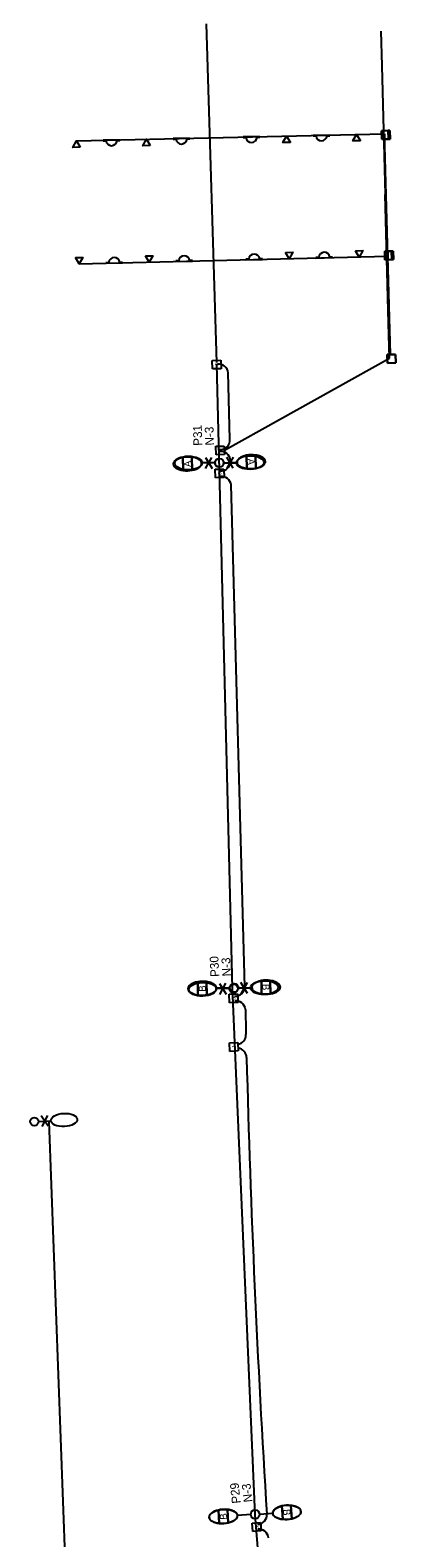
# Model space of a CAD drawing. Extents: x 925407 to 930994, y 604905 to 637063.
# Drawn here: x 929545 to 929754, y 612493 to 613355 of the extents above; entities that cross this region are included whole.
import ezdxf

# ---------------------------------------------------------------- set-up
doc = ezdxf.new("R2010")
doc.units = 0
for name, color, linetype in [('ActivePointCell_dp', 7, 'Continuous'), ('Conduit', 7, 'Continuous'), ('ConduitDB', 7, 'Continuous'), ('ConduitJB', 7, 'Continuous'), ('ConduitOT', 7, 'Continuous'), ('GPKDrCellIns_dp', 7, 'Continuous'), ('LightingMisc', 7, 'Continuous'), ('LiteCond_ep', 7, 'Continuous'), ('Miscellaneous2', 7, 'Continuous'), ('Miscellaneous9', 7, 'Continuous'), ('PoleLight', 7, 'Continuous'), ('PoleLight_ep', 7, 'Continuous'), ('PullBox', 7, 'Continuous')]:
    doc.layers.add(name, color=color, linetype=linetype)

msp = doc.modelspace()

# ---------------------------------------------------------------- linework, layer by layer
at = {"layer": 'Conduit'}
msp.add_line((929651.54, 613165.32), (929645.79, 613359.05), dxfattribs=at)
at = {"layer": 'ConduitDB'}
msp.add_line((929655.91, 613115.2), (929750.25, 613167.98), dxfattribs=at)
at = {"layer": 'ConduitJB'}
for p, q in [((929571.45, 613292.07), (929747.38, 613296.17)), ((929750.86, 613169.96), (929747.38, 613296.17)), ((929573.02, 613221.75), (929749.31, 613226.14))]:
    msp.add_line(p, q, dxfattribs=at)
at = {"layer": 'ConduitOT'}
for p, q in [((929659.06, 613121.61), (929658.07, 613159.53)), ((929659.4, 613108.69), (929659.38, 613109.59)), ((929667.52, 612808.4), (929659.75, 613095.39))]:
    msp.add_line(p, q, dxfattribs=at)
for centre, radius, start, end in [((929652.59, 613159), 5.5, 5.56734, 96.33453), ((929653.58, 613121.09), 5.5, 266.74857, 5.47711), ((929653.9, 613109.06), 5.5, 5.53953, 96.33453), ((929653.9, 613108.86), 5.5, 266.74857, 357.51576), ((929654.28, 613094.85), 5.5, 5.56734, 96.33453), ((929662.02, 612808.62), 5.5, 266.96058, 357.72777), ((929662.46, 612794.99), 5.5, 5.56734, 96.33453), ((936541.94, 612938.58), 6875.49, 181.192383, 181.311805), ((929662.76, 612781.04), 5.5, 279.20217, 1.54155), ((929663.11, 612767.88), 5.5, 1.54155, 83.37973), ((936541.9, 612942.08), 6875.49, 181.450542, 183.628101), ((929674.7, 612506.68), 5.5, 272.51439, 3.28158), ((929675.59, 612492.94), 5.5, 5.56734, 96.33453)]:
    msp.add_arc(centre, radius, start, end, dxfattribs=at)
at = {"layer": 'GPKDrCellIns_dp'}
for p, q in [((929745.22, 613354.91), (929745.76, 613334.92)), ((929745.76, 613334.92), (929747.73, 613261.44)), ((929749.71, 613187.97), (929747.73, 613261.44)), ((929750.25, 613167.98), (929749.71, 613187.97))]:
    msp.add_line(p, q, dxfattribs=at)
at = {"layer": 'LightingMisc'}
for p, q in [((929596.22, 613292.6), (929586.7, 613292.47)), ((929586.7, 613292.47), (929586.71, 613292.15)), ((929586.71, 613292.15), (929588.31, 613292.18)), ((929594.62, 613292.26), (929596.22, 613292.28)), ((929596.22, 613292.28), (929596.22, 613292.6)), ((929636.21, 613293.53), (929626.69, 613293.4)), ((929626.69, 613293.4), (929626.69, 613293.09)), ((929626.69, 613293.09), (929628.3, 613293.11)), ((929634.61, 613293.19), (929636.21, 613293.21)), ((929636.21, 613293.21), (929636.21, 613293.53)), ((929676.2, 613294.46), (929666.68, 613294.33)), ((929666.68, 613294.33), (929666.68, 613294.02)), ((929666.68, 613294.02), (929668.29, 613294.04)), ((929674.6, 613294.12), (929676.2, 613294.15)), ((929676.2, 613294.15), (929676.2, 613294.46)), ((929716.16, 613295.39), (929706.64, 613295.27)), ((929706.64, 613295.27), (929706.64, 613294.95)), ((929706.64, 613294.95), (929708.24, 613294.97)), ((929714.56, 613295.06), (929716.16, 613295.08)), ((929716.16, 613295.08), (929716.16, 613295.39)), ((929589.82, 613222.51), (929588.22, 613222.48)), ((929588.22, 613222.48), (929588.22, 613222.17)), ((929588.22, 613222.17), (929597.74, 613222.32)), ((929597.74, 613222.64), (929596.13, 613222.61)), ((929597.74, 613222.32), (929597.74, 613222.64)), ((929629.83, 613223.48), (929628.23, 613223.44)), ((929628.23, 613223.44), (929628.24, 613223.12)), ((929628.24, 613223.12), (929637.76, 613223.36)), ((929637.75, 613223.68), (929636.15, 613223.64)), ((929637.76, 613223.36), (929637.75, 613223.68)), ((929669.82, 613224.48), (929668.22, 613224.44)), ((929668.22, 613224.44), (929668.23, 613224.12)), ((929668.23, 613224.12), (929677.74, 613224.36)), ((929677.73, 613224.67), (929676.13, 613224.63)), ((929677.74, 613224.36), (929677.73, 613224.67)), ((929709.81, 613225.47), (929708.21, 613225.43)), ((929708.21, 613225.43), (929708.21, 613225.11)), ((929708.21, 613225.11), (929717.73, 613225.35)), ((929717.72, 613225.67), (929716.12, 613225.63)), ((929717.73, 613225.35), (929717.72, 613225.67))]:
    msp.add_line(p, q, dxfattribs=at)
for points in [[(929573.63, 613288.44), (929569.42, 613288.33), (929571.44, 613292.04)], [(929613.62, 613289.4), (929609.4, 613289.3), (929611.42, 613293)], [(929693.6, 613291.26), (929689.38, 613291.16), (929691.4, 613294.86)], [(929733.59, 613292.19), (929729.37, 613292.09), (929731.39, 613295.8)], [(929730.77, 613229.3), (929734.99, 613229.4), (929732.97, 613225.7)], [(929570.82, 613225.35), (929575.04, 613225.45), (929573.02, 613221.75)], [(929610.81, 613226.34), (929615.02, 613226.45), (929613, 613222.74)], [(929690.78, 613228.34), (929695, 613228.44), (929692.98, 613224.74)]]:
    msp.add_lwpolyline(points, close=True, dxfattribs=at)
for centre, start, end in [((929591.46, 613292.54), 186.51447, 355.03606), ((929631.45, 613293.47), 186.51447, 355.03606), ((929671.44, 613294.4), 186.51447, 355.03606), ((929711.4, 613295.33), 186.51447, 355.03606), ((929592.98, 613222.24), 6.65968, 175.18127), ((929633, 613223.24), 7.17855, 175.70014), ((929672.98, 613224.24), 7.17855, 175.70014), ((929712.97, 613225.23), 7.17855, 175.70014)]:
    msp.add_arc(centre, 3.17, start, end, dxfattribs=at)
at = {"layer": 'LiteCond_ep'}
for p, q in [((929749.56, 613297.98), (929745.66, 613297.87)), ((929745.66, 613297.87), (929745.71, 613296.13)), ((929747.38, 613296.17), (929745.71, 613296.13)), ((929745.71, 613296.13), (929747.38, 613296.17)), ((929745.71, 613296.13), (929745.8, 613293.03)), ((929745.8, 613293.03), (929747.46, 613293.07)), ((929747.46, 613293.07), (929747.38, 613296.17)), ((929747.38, 613296.17), (929747.46, 613293.07)), ((929747.46, 613293.07), (929749.69, 613293.14)), ((929750.5, 613298.01), (929749.56, 613297.98)), ((929749.69, 613293.14), (929749.56, 613297.98)), ((929749.56, 613297.98), (929749.69, 613293.14)), ((929749.69, 613293.14), (929750.64, 613293.16)), ((929750.64, 613293.16), (929750.5, 613298.01)), ((929749.23, 613229.05), (929747.51, 613229)), ((929747.51, 613229), (929747.6, 613226.1)), ((929749.31, 613226.14), (929747.6, 613226.1)), ((929747.6, 613226.1), (929749.31, 613226.14)), ((929747.6, 613226.1), (929747.65, 613224.16)), ((929747.65, 613224.16), (929749.36, 613224.21)), ((929751.42, 613229.11), (929749.23, 613229.05)), ((929749.31, 613226.14), (929749.23, 613229.05)), ((929749.36, 613224.21), (929749.31, 613226.14)), ((929749.36, 613224.21), (929751.55, 613224.27)), ((929752.36, 613229.14), (929751.42, 613229.11)), ((929751.55, 613224.27), (929751.42, 613229.11)), ((929751.42, 613229.11), (929751.55, 613224.27)), ((929751.55, 613224.27), (929752.49, 613224.29)), ((929752.49, 613224.29), (929752.36, 613229.14)), ((929753.84, 613165.2), (929753.7, 613170.04)), ((929660.59, 612807.71), (929651.56, 613164.42)), ((929749, 613165.06), (929753.84, 613165.2)), ((929673.41, 612506.71), (929660.59, 612807.71)), ((929565.17, 612477.97), (929555.86, 612731.45)), ((929697.94, 612206.69), (929673.41, 612506.71))]:
    msp.add_line(p, q, dxfattribs=at)
for points in [[(929749.23, 613229.05), (929749.31, 613226.14), (929749.36, 613224.21)], [(929753.7, 613170.04), (929753.01, 613170.02), (929750.86, 613169.96), (929748.86, 613169.91)], [(929748.86, 613169.91), (929748.92, 613167.94), (929749, 613165.06)]]:
    msp.add_lwpolyline(points, dxfattribs=at)
at = {"layer": 'Miscellaneous2'}
for p, q in [((929632.21, 613111.29), (929632.21, 613111.29)), ((929632.21, 613111.29), (929632.43, 613103.63)), ((929637.53, 613103.78), (929637.31, 613111.44)), ((929637.31, 613111.44), (929637.31, 613111.44)), ((929668.55, 613112.35), (929668.55, 613112.35)), ((929668.55, 613112.35), (929668.77, 613104.69)), ((929673.87, 613104.83), (929673.64, 613112.5)), ((929673.64, 613112.5), (929673.64, 613112.5)), ((929640.69, 612811.34), (929640.69, 612811.34)), ((929640.69, 612811.34), (929640.84, 612803.68)), ((929645.94, 612803.78), (929645.79, 612811.44)), ((929645.79, 612811.44), (929645.79, 612811.44)), ((929677.04, 612812.04), (929677.04, 612812.04)), ((929677.04, 612812.04), (929677.18, 612804.37)), ((929682.28, 612804.47), (929682.14, 612812.13)), ((929682.14, 612812.13), (929682.14, 612812.13)), ((929652.53, 612509.38), (929652.53, 612509.38)), ((929652.53, 612509.38), (929653.02, 612501.73)), ((929658.11, 612502.06), (929657.62, 612509.71)), ((929657.62, 612509.71), (929657.62, 612509.71)), ((929688.81, 612511.72), (929688.81, 612511.72)), ((929688.81, 612511.72), (929689.3, 612504.07)), ((929694.39, 612504.39), (929693.9, 612512.04)), ((929693.9, 612512.04), (929693.9, 612512.04))]:
    msp.add_line(p, q, dxfattribs=at)
for centre, major_axis, start_param, end_param in [((929634.87, 613107.54), (8.07, 0.23), 1.249648, 1.891946), ((929671.21, 613108.59), (8.07, 0.23), 1.249648, 1.891946), ((929634.87, 613107.54), (8.07, 0.23), 4.391271, 5.033538), ((929634.87, 613107.54), (8.07, 0.23), 4.391241, 4.391271), ((929671.21, 613108.59), (8.07, 0.23), 4.391271, 5.033538), ((929671.21, 613108.59), (8.07, 0.23), 4.391241, 4.391271), ((929643.31, 612807.56), (8.08, 0.15), 1.249648, 1.891946), ((929679.66, 612808.25), (8.08, 0.15), 1.249648, 1.891946), ((929643.31, 612807.56), (8.08, 0.15), 4.391271, 5.033538), ((929643.31, 612807.56), (8.08, 0.15), 4.391241, 4.391271), ((929679.66, 612808.25), (8.08, 0.15), 4.391271, 5.033538), ((929679.66, 612808.25), (8.08, 0.15), 4.391241, 4.391271), ((929655.32, 612505.72), (8.06, 0.52), 1.249648, 1.891946), ((929691.6, 612508.05), (8.06, 0.52), 1.249648, 1.891946), ((929655.32, 612505.72), (8.06, 0.52), 4.391271, 5.033538), ((929655.32, 612505.72), (8.06, 0.52), 4.391241, 4.391271), ((929691.6, 612508.05), (8.06, 0.52), 4.391271, 5.033538), ((929691.6, 612508.05), (8.06, 0.52), 4.391241, 4.391271)]:
    msp.add_ellipse(centre, major_axis=major_axis, ratio=0.5, start_param=start_param, end_param=end_param, dxfattribs=at)
at = {"layer": 'PoleLight'}
for p, q in [((929632.43, 613103.63), (929632.21, 613111.29)), ((929637.31, 613111.44), (929637.53, 613103.78)), ((929668.77, 613104.69), (929668.55, 613112.35)), ((929673.64, 613112.5), (929673.87, 613104.83)), ((929650.51, 613107.99), (929642.94, 613107.77)), ((929655.56, 613108.14), (929663.13, 613108.36)), ((929640.84, 612803.68), (929640.69, 612811.34)), ((929645.79, 612811.44), (929645.94, 612803.78)), ((929658.96, 612807.86), (929651.39, 612807.71)), ((929664.01, 612807.95), (929671.58, 612808.1)), ((929677.18, 612804.37), (929677.04, 612812.04)), ((929682.14, 612812.13), (929682.28, 612804.47)), ((929653.02, 612501.73), (929652.53, 612509.38)), ((929657.62, 612509.71), (929658.11, 612502.06)), ((929670.94, 612506.73), (929663.38, 612506.24)), ((929675.98, 612507.05), (929683.54, 612507.54)), ((929689.3, 612504.07), (929688.81, 612511.72)), ((929693.9, 612512.04), (929694.39, 612504.39))]:
    msp.add_line(p, q, dxfattribs=at)
for centre in [(929653.04, 613108.06), (929653.04, 613108.06), (929661.49, 612807.91), (929661.49, 612807.91), (929673.46, 612506.89), (929673.46, 612506.89)]:
    msp.add_circle(centre, 2.52, dxfattribs=at)
for centre, major_axis in [((929634.87, 613107.54), (8.07, 0.23)), ((929671.21, 613108.59), (8.07, 0.23)), ((929643.31, 612807.56), (8.08, 0.15)), ((929679.66, 612808.25), (8.08, 0.15)), ((929655.32, 612505.72), (8.06, 0.52)), ((929691.6, 612508.05), (8.06, 0.52))]:
    msp.add_ellipse(centre, major_axis=major_axis, ratio=0.5, dxfattribs=at)
for centre, major_axis, start_param, end_param in [((929634.87, 613107.54), (8.07, 0.23), 1.891945, 4.391241), ((929634.87, 613107.54), (8.07, 0.23), 0.847605, 1.249648), ((929634.87, 613107.54), (8.07, 0.23), 0, 0.847605), ((929671.21, 613108.59), (8.07, 0.23), 1.891945, 4.391241), ((929671.21, 613108.59), (8.07, 0.23), 0.847605, 1.249648), ((929671.21, 613108.59), (8.07, 0.23), 5.033538, 6.283185), ((929671.21, 613108.59), (8.07, 0.23), 0, 0.847605), ((929634.87, 613107.54), (8.07, 0.23), 5.033538, 6.283185), ((929643.31, 612807.56), (8.08, 0.15), 1.891945, 4.391241), ((929643.31, 612807.56), (8.08, 0.15), 0.847605, 1.249648), ((929643.31, 612807.56), (8.08, 0.15), 5.033538, 6.283185), ((929643.31, 612807.56), (8.08, 0.15), 0, 0.847605), ((929679.66, 612808.25), (8.08, 0.15), 1.891945, 4.391241), ((929679.66, 612808.25), (8.08, 0.15), 0.847605, 1.249648), ((929679.66, 612808.25), (8.08, 0.15), 5.033538, 6.283185), ((929679.66, 612808.25), (8.08, 0.15), 0, 0.847605), ((929655.32, 612505.72), (8.06, 0.52), 1.891945, 4.391241), ((929655.32, 612505.72), (8.06, 0.52), 0.847605, 1.249648), ((929655.32, 612505.72), (8.06, 0.52), 5.033538, 6.283185), ((929655.32, 612505.72), (8.06, 0.52), 0, 0.847605), ((929691.6, 612508.05), (8.06, 0.52), 1.891945, 4.391241), ((929691.6, 612508.05), (8.06, 0.52), 0.847605, 1.249648), ((929691.6, 612508.05), (8.06, 0.52), 5.033538, 6.283185), ((929691.6, 612508.05), (8.06, 0.52), 0, 0.847605)]:
    msp.add_ellipse(centre, major_axis=major_axis, ratio=0.5, start_param=start_param, end_param=end_param, dxfattribs=at)
at = {"layer": 'PoleLight_ep'}
for p, q in [((929645.13, 613111.15), (929648.85, 613104.81)), ((929645.17, 613104.78), (929648.8, 613111.18)), ((929660.95, 613104.98), (929657.23, 613111.32)), ((929660.9, 613111.34), (929657.27, 613104.95)), ((929650.59, 613108.05), (929643.24, 613107.99)), ((929655.49, 613108.08), (929662.84, 613108.13)), ((929658.66, 612807.49), (929651.31, 612807.27)), ((929653.13, 612810.47), (929656.99, 612804.21)), ((929653.32, 612804.11), (929656.81, 612810.58)), ((929663.56, 612807.63), (929670.91, 612807.84)), ((929669.09, 612804.64), (929665.23, 612810.9)), ((929668.9, 612811.01), (929665.41, 612804.54)), ((929549.72, 612731.58), (929556.79, 612731.96)), ((929555.19, 612728.8), (929551.32, 612734.74)), ((929554.86, 612734.93), (929551.65, 612728.61))]:
    msp.add_line(p, q, dxfattribs=at)
for centre, radius in [((929653.04, 613108.06), 2.45), ((929661.11, 612807.56), 2.45), ((929547.36, 612731.45), 2.36)]:
    msp.add_circle(centre, radius, dxfattribs=at)
for centre, major_axis in [((929635.4, 613107.94), (-7.84, -0.06)), ((929670.68, 613108.19), (7.84, 0.06)), ((929643.48, 612807.05), (-7.84, -0.23)), ((929678.74, 612808.07), (7.84, 0.23)), ((929564.34, 612732.38), (7.55, 0.41))]:
    msp.add_ellipse(centre, major_axis=major_axis, ratio=0.5, dxfattribs=at)
at = {"layer": 'PullBox'}
for p, q in [((929745.66, 613297.87), (929750.5, 613298.01)), ((929745.8, 613293.03), (929745.66, 613297.87)), ((929750.64, 613293.16), (929745.8, 613293.03)), ((929750.5, 613298.01), (929750.64, 613293.16)), ((929747.51, 613229), (929752.36, 613229.14)), ((929747.65, 613224.16), (929747.51, 613229)), ((929752.49, 613224.29), (929747.65, 613224.16)), ((929752.36, 613229.14), (929752.49, 613224.29)), ((929748.86, 613169.91), (929753.7, 613170.04)), ((929749, 613165.06), (929748.86, 613169.91)), ((929753.7, 613170.04), (929753.84, 613165.2)), ((929649.03, 613166.57), (929653.87, 613166.71)), ((929649.17, 613161.73), (929649.03, 613166.57)), ((929654.01, 613161.87), (929649.17, 613161.73)), ((929653.87, 613166.71), (929654.01, 613161.87)), ((929753.84, 613165.2), (929749, 613165.06)), ((929651, 613117.49), (929655.85, 613117.62)), ((929651.14, 613112.65), (929651, 613117.49)), ((929655.85, 613117.62), (929655.98, 613112.78)), ((929655.98, 613112.78), (929651.14, 613112.65)), ((929650.73, 613104.35), (929655.58, 613104.48)), ((929650.87, 613099.5), (929650.73, 613104.35)), ((929655.58, 613104.48), (929655.71, 613099.64)), ((929655.71, 613099.64), (929650.87, 613099.5)), ((929658.64, 612804.21), (929663.48, 612804.44)), ((929658.88, 612799.37), (929658.64, 612804.21)), ((929663.72, 612799.6), (929658.88, 612799.37)), ((929663.48, 612804.44), (929663.72, 612799.6)), ((929658.75, 612776.42), (929663.58, 612776.65)), ((929658.98, 612771.58), (929658.75, 612776.42)), ((929663.58, 612776.65), (929663.82, 612771.81)), ((929663.82, 612771.81), (929658.98, 612771.58)), ((929671.73, 612501.93), (929676.56, 612502.3)), ((929672.1, 612497.1), (929671.73, 612501.93)), ((929676.93, 612497.47), (929672.1, 612497.1)), ((929676.56, 612502.3), (929676.93, 612497.47))]:
    msp.add_line(p, q, dxfattribs=at)

# ---------------------------------------------------------------- texts
at = {"layer": 'ActivePointCell_dp'}
for s, rotation, p in [('P31', 91.4753, (929643.28, 613117.85)), ('N-3', 91.4753, (929649.97, 613118.02)), ('P30', 92.67002, (929653.01, 612814.27)), ('N-3', 92.67002, (929659.71, 612814.58)), ('P29', 96.09476, (929665.26, 612513.35)), ('N-3', 96.09476, (929671.92, 612514.06))]:
    msp.add_text(s, height=5, rotation=rotation, dxfattribs=at).set_placement(p)
at = {"layer": 'Miscellaneous9'}
for s, rotation, p in [('A', 91.66421, (929636.96, 613105.69)), ('A', 271.66421, (929669.11, 613110.43)), ('B', 91.08953, (929645.39, 612805.74)), ('B', 271.08953, (929677.58, 612810.08)), ('B', 93.68152, (929657.48, 612503.99)), ('B', 273.68152, (929689.44, 612509.78))]:
    msp.add_text(s, height=4.08, rotation=rotation, dxfattribs=at).set_placement(p)
at = {"layer": 'PullBox'}
for rotation, p in [(91.60658, (929652.51, 613163.59)), (91.60658, (929654.48, 613114.5)), (91.60658, (929654.21, 613101.36)), (92.74454, (929662.18, 612801.3)), (92.74454, (929662.28, 612773.51)), (94.42446, (929675.35, 612499.12))]:
    msp.add_text('J', height=1.94, rotation=rotation, dxfattribs=at).set_placement(p)

doc.saveas('drawing.dxf')
